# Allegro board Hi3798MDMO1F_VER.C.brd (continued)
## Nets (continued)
IR_IN: D3.1 J3.3 R140.1 U1.58
LED0_BASE: R26.2 R67.2 U1.151
LED0_LINK_ACT: R30.2 R79.2 U1.150
LED_CTRL: R3.1 R31.2 R77.1 U1.57
LED_GREEN: J3.1 LED1.3 Q2.3 R34.2
LED_RED: J3.5 LED1.1 Q1.3 R2.2 R22.1
NF_ALE_EMMC_PWREN: U1.80 U19.17
NF_CLE: U1.81 U19.16
NF_CSN0_EMMC_CMD: R212.2 U1.82 U19.9 U22.W5
NF_DQ0_EMMC_D0: R189.2 U1.77 U19.29 U22.H3
NF_DQ1_EMMC_D1: R12.2 U1.76 U19.30 U22.H4
NF_DQ2_EMMC_D2: R29.2 U1.75 U19.31 U22.H5
NF_DQ3_EMMC_D3: R58.2 U1.73 U19.32 U22.J2
NF_DQ4_EMMC_D4: R176.2 U1.72 U19.41 U22.J3
NF_DQ5_EMMC_D5: R177.2 U1.71 U19.42 U22.J4
NF_DQ6_EMMC_D6: R188.2 U1.70 U19.43 U22.J5
NF_DQ7_EMMC_D7_BOOT_SEL0: R33.1 R202.2 U1.69 U19.44 U22.J6
NF_RDY0_EMMC_RST: C115.1 R203.2 U1.85 U19.7 U22.U5
NF_REN_EMMC_CLK: R59.1 U19.8 U22.W6
NF_WEN_EMMC_DET: R56.2 U1.79 U19.18
NF_WP: R89.1 R215.2 U19.19
PWR_OFF/ON: R40.1 R41.1 U1.102
RECOVERY: C138.2 R25.2 S1.2 U1.103
RF0: C89.1 L1.2 U7.3
RF1: C56.1 L7.2 U2.7 U7.2
RFF0: C88.1 J9.1 L1.1
RFF1: C50.1 J8.1 L7.1
RX+_PHY0: R97.1 U1.143 U8.2 U8.7
RX-_PHY0: R96.1 U1.142 U8.1 U8.8
SPDIF_OUT_BOOT_SEL1: R39.1 U1.117
STANDBY_PWROFF: C119.1 LB3.2 R5.1 R47.1 R73.1 R88.1 R98.1
TX+_PHY0: R93.1 U1.146 U8.4 U8.5
TX-_PHY0: R94.1 U1.145 U8.3 U8.6
UART0_RXD: J18.2 R136.1 U1.60
UART0_TXD: J18.3 R135.2 U1.61
USB0_DM: C103.1 D5.1 J12.2 U1.140
USB0_DP: C106.1 D4.1 J12.3 U1.141
USB01_1V1: C334.1 C336.1 LB31.2 U1.137
USB01_3V3: C10.1 C182.1 LB20.2 U1.139
USB1_DM: J2.4 U1.135 U2.4 U7.7
USB1_DP: J2.3 U1.136 U2.2 U7.6
USB2_DM: D7.1 J7.2 U1.89
USB2_DP: D6.1 J7.3 U1.90
USB03_VBUS: C60.1 C265.1 C372.1 J7.1 J12.1 LB2.1 U26.5
USB_BOOT: R42.2 U1.108
VDAC_3V3: C9.1 C85.1 LB14.2 U1.112
XIN: C364.1 R1.2 U1.63 X2.1
XOUT: R1.1 R14.1 U1.64
$4N588: C84.1 R10.1 R52.1 U15.5
$4N589: L4.1 U15.3
$4N593: C30.1 R6.2 R47.2 U15.1
$4N676: C43.1 C71.1 R7.2 R21.1
$4N677: C76.1 R53.1 R70.1 R99.2 U11.6
$4N679: L2.1 U11.3
$4N687: C8.1 R73.2 U11.1
$4N714: C82.1 R13.2 R101.1 R110.1 U13.6
$4N715: C45.1 C72.1 R23.1 R102.2
$4N716: R102.1 R110.2
$4N719: L3.1 U13.3
$4N724: C5.1 R5.2 U13.1
$4N894: R7.1 R70.2
$4N901: R100.1 R105.1 U14.5
$4N903: D2.1 R95.1 U14.1
$4N904: C83.2 R104.1
$4N905: C24.1 C83.1 U14.6
$4N906: R4.2 U14.7
$4N919: C44.1 U14.8
$4N923: C65.1 R95.2
$4N925: C65.2 L5.1 U14.3
$4N944: J1.1 J5.2 J10.1 R81.1
$5N541: Q4.3 R118.2 R144.2
$5N542: C6.2 Q13.1 Q14.1 R118.1
$5N549: Q4.1 R98.2
$6N188: C365.1 R14.2 X2.3
$6N1407: R173.1 U1.149
$6N2385: R82.2 R85.2 U1.138
$6N2411: C136.1 R42.1 S2.1 S2.2
$6N2437: R59.2 U1.84
$6N2445: C118.1 LB3.1 U1.59
$7N1408: C250.2 U1.113
$7N1763: R32.2 U1.111
$7N2000: R24.2 R87.2 U1.87
$8N1506: R45.1 U1.54
$8N1694: R18.2 U1.17
$8N1695: R35.2 U1.18
$8N1696: R36.2 U1.14
$8N1697: R37.2 U1.15
$9N2352: C255.2 U1.55
$9N2555: C122.1 LB5.2 U1.65
$10N1056: C328.1 R11.2 R15.1
$10N1121: R46.2 U3.L8
$11N1393: C330.1 R16.2 R17.1
$11N1414: R71.2 U6.L8
$12N1655: R49.2 U19.38
$12N1661: R57.1 U19.39
$12N1670: C123.1 C124.1 U22.K2
$13N803: R220.1 U26.3
$13N804: R106.2 U26.4
$14N721: Q2.1 R22.2
$14N731: Q1.1 R3.2
$15N1021: C351.2 R193.1
$15N1022: C55.1 R27.2 U5.2
$15N1025: C317.1 R19.1 R27.1 R193.2
$15N1029: C55.2 R19.2 R74.2 R146.1 U5.3
$15N1031: C54.2 R28.1 U5.13
$15N1032: C54.1 R20.1 R72.1 R145.1 U5.12
$15N1036: C350.1 R194.2
$15N1037: C316.1 R20.2 R28.2 R194.1
$15N1074: R43.2 R44.1 R48.2
$15N1075: R43.1 U5.11
$15N1082: C32.1 U5.7
$15N1083: C33.2 U5.6
$15N1085: C32.2 U5.8
$15N1114: C363.1 R66.1 U5.5
$16N1065: C154.1 C297.1 T2.7
$16N1066: J25.9 R67.1
$16N1067: J25.11 R79.1
$16N1068: J25.7 J25.8 R270.2
$16N1069: R271.2 T2.15
$16N1070: R269.2 T2.10
$16N1072: J25.6 T2.9
$16N1073: J25.3 T2.11
$16N1074: C23.1 R269.1 R270.1 R271.1 R272.1
$16N1075: J25.1 T2.16
$16N1076: J25.2 T2.14
$16N1077: J25.4 J25.5 R272.2
$16N1078: C153.1 C307.1 T2.2
$16N1097: R96.2 T2.8
$16N1098: R97.2 T2.6
$16N1099: R94.2 T2.3
$16N1100: R93.2 T2.1
$18N796: D19.1 R268.1

Pads without a net: ID1 1; ID2 1; ID3 1; ID4 1; ID5 1; ID6 1; J2 1 6 8 11; J26 14; M20 1; M21 1; T2 4 5 12 13; U1 56 99 100 101 152 153 154 155 156 157 159 160 161 162; U2 3; U3 J1 J9 L1 L9; U6 J1 J9 L1 L9; U7 4 9 10; U11 5; U13 5; U19 3 4 5 6 10 11 14 15 20 21 22 26 27 28 33 35 40 45 46 47; U22 A4 A6 A9 A11 AA1 AA2 AA7 AA8 AA9 AA10 AA11 AA12 AA13 AA14 AE1 AE14 AG2 AG13 AH4 AH6 AH9 AH11 B2 B13 D1 D14 H1 H2 H6 H7 H8 H9 H10 H11 H12 H13 H14 J1 J7 J8 J9 J10 J11 J12 J13 J14 K1 K3 K5 K7 K8 K9 K10 K11 K12 K13 K14 L1 L2 L3 L4 L12 L13 L14 M1 M2 M3 M5 M8 M9 M10 M12 M13 M14 N1 N2 N3 N10 N12 N13 N14 P1 P2 P3 P10 P12 P13 P14 R1 R2 R3 R5 R12 R13 R14 T1 T2 T3 T5 T12 T13 T14 U1 U2 U3 U6 U7 U10 U12 U13 U14 V1 V2 V3 V12 V13 V14 W1 W2 W3 W7 W8 W9 W10 W11 W12 W13 W14 Y1 Y3 Y6 Y7 Y8 Y9 Y10 Y11 Y12 Y13 Y14

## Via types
v1: diameter 0.457, hole 0.203, TOP to BOTTOM, 423 vias
v2: diameter 0.508, hole 0.254, TOP to BOTTOM, 1803 vias
v3: diameter 0.635, hole 0.305, TOP to BOTTOM, 36 vias

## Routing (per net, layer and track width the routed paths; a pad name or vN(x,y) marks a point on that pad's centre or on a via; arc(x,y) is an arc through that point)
1V1_CORE: length 71.9
  TOP w0.203: U1.168 v2(59.58,56.7) ; U1.118 78.22,59.92 v1(78.4,59.74) ; v2(59.58,49.75) 59.33,49.5 U1.186 ; U1.202 v2(59.58,43.1) ; U1.193 v2(59.58,46.7) ; U1.134 71.82,60.03 v1(72.1,59.76) ; U1.86 83.18,49.9 82.86,49.58 v1(82.86,49.52) ; v2(59.66,38.3) U1.214 ; U1.30 v2(72.22,36.47) ; v1(82.86,57.7) 82.86,57.68 82.86,57.68 82.86,57.68 83.04,57.5 U1.105 ; U1.39 v2(75.82,36.47) ; U1.4 v2(61.82,36.47) ; U1.10 v2(64.22,36.47) ; U1.49 v2(79.82,36.47) ; U1.158 v2(62.22,59.58) ; U1.78 v1(82.86,46.7) ; U1.180 v2(59.58,51.9)
  TOP w0.381: v2(85.7,35.02) 85.97,34.75 89.5,34.75 90.71,33.54 90.71,26.53 C82.2
  TOP w0.508: R101.2 C82.2
  BOTTOM w0.305: C189.1 59.58,51.9 v2(59.58,51.9) ; C62.1 59.52,56.76 v2(59.58,56.7) ; v2(64.22,36.47) 64.22,36.44 C19.1 ; C193.1 61.82,36.44 61.82,36.44 v2(61.82,36.47) ; v2(79.82,36.47) 79.82,36.44 79.82,36.44 C64.1 ; C107.1 v2(72.22,36.47) ; C129.1 v1(82.86,49.52) ; C120.1 v2(75.82,36.47) ; v1(82.86,57.7) 82.86,57.71 82.98,57.83 C128.1
  BOTTOM w0.381: C127.1 59.66,38.3 v2(59.66,38.3) 59.67,38.3 60.55,38.3 60.55,38.3 60.84,38.3 v2(62.18,39.64) ; C121.1 59.58,43.1 v2(59.58,43.1) v2(62.17,43.1) ; v2(61.54,51.9) v2(59.58,51.9) ; C66.1 78.61,59.95 v1(78.4,59.74) ; C130.1 83.54,46.7 v1(82.86,46.7) ; v2(62.22,59.58) 62.22,59.61 62.23,59.61 C70.1 ; LB31.1 72.86,58.1 73.25,58.49 73.25,59.43 72.92,59.76 v1(72.1,59.76) 72.03,59.82 C126.1 ; v2(62.17,46.7) v2(59.58,46.7) 59.4,46.52 C73.1 ; v2(79.82,36.47) v2(79.82,38.29) ; v2(64.22,36.47) 64.22,37.45 64.21,37.46 64.22,37.47 v2(64.22,38.73) ; v2(62.71,38.73) 61.82,37.84 v2(61.82,36.47) ; v2(72.22,36.47) v2(72.22,38.29) ; C1.1 59.19,49.75 v2(59.58,49.75) v2(61.54,49.75) ; v2(61.54,56.7) v2(59.58,56.7) ; v2(75.82,36.47) v2(75.82,38.29)
  vias: v2(76.94,59.56) v2(76.94,58.82) v2(81.71,45.18) v2(81.92,37.79) v2(82.55,37.03) v2(82.68,37.79) v2(83.19,36.39) v2(83.31,35.5) v2(84.18,35.02) v2(84.18,34.26) v2(84.94,35.02) v2(84.94,34.26) v2(85.7,34.26)
1V1_CPU: length 13.6
  TOP w0.203: U1.98 85.53,54.7
  TOP w0.381: v2(106.8,62.23) C76.2 R53.2
  BOTTOM w0.381: v2(106.8,62.23) 101.74,62.23 v2(98.01,58.5)
  vias: v1(82.88,53.77) v1(82.86,52.44) v1(82.86,51.78) v2(85.01,52.32) v2(85.45,54.53) v2(85.45,53.71) v2(85.45,52.9) v2(93.98,54.76) v2(93.95,53.92) v2(94.95,53.89) v2(96.01,53.89) v2(98.26,55.52) v2(98.26,54.76) v2(98.26,53.99) v2(99.02,55.52) v2(99.02,54.76) v2(99.02,53.99)
1V5_DDR3: length 66.4
  TOP w0.203: v2(81.17,36.47) 81.42,36.22 U1.53 ; U1.13 v2(65.42,36.46) ; U1.174 v2(59.58,54.3) ; U1.165 v2(59.58,57.9) ; U1.183 v2(59.58,50.7) ; U1.208 v2(59.58,40.7) ; U1.7 v2(63.02,36.46) ; U1.25 v2(70.22,36.47) ; U1.190 59.33,47.9 v2(59.58,47.65) ; U1.35 v2(74.22,36.47) ; U1.199 v2(59.58,44.3) ; U1.205 v2(59.58,41.9) ; U1.171 v2(59.58,55.5) ; U1.196 v2(59.58,45.5) ; U1.44 v2(77.82,36.47) ; U1.16 v2(66.62,36.46)
  TOP w0.254: 14.27,53.54 14.27,52.45 13.08,51.26 v2(13.08,50.62) ; U6.F1 49.24,38.74 v1(49.24,39.26) ; C84.2 R10.2 6.63,50.65 v2(6.6,50.62)
  TOP w0.305: U6.D9 v1(50.85,31.79) ; v1(42.05,39.36) U6.R1 ; U3.C9 v1(51.65,48.21) ; U3.K8 v1(46.45,49.95) ; U6.C1 v1(51.65,39.29) ; v1(48.44,50.88) 48.45,50.87 U3.G7 ; U6.N9 v1(43.65,31.79) ; U3.F1 49.25,55.77 49.25,55.77 v1(49.25,55.82) ; U3.R9 v1(42.05,48.21) ; U3.D9 v1(50.85,48.21) ; U6.G7 v2(48.05,34.34) ; U6.R9 42.05,32.07 41.83,31.85 v1(41.83,31.85) ; U3.B2 v1(52.85,54.75) U3.A1 ; v1(43.65,39.36) U6.N1 ; U6.C9 v1(51.65,31.79) ; U6.A8 v1(53.86,33.14) ; U6.D2 v1(51.25,37.54) ; U6.E9 v1(50.05,31.79) ; U6.K8 v1(46.45,33.54) ; U6.B2 v1(52.85,38.35) U6.A1 v1(53.25,39.29) ; U1.1 v2(60.57,36.52) ; U3.H9 v1(47.65,48.21) ; U6.K2 v1(45.65,38.34) ; U3.E9 v1(50.05,48.21) ; v1(51.65,55.69) U3.C1 ; U6.H9 v1(47.65,31.79) ; v1(42.05,55.77) U3.R1 ; v1(43.65,55.77) U3.N1 ; U3.K2 v1(45.65,54.75) ; U3.N9 v1(43.65,48.21) ; U3.A8 v1(53.65,49.15) ; U3.H2 v2(48.05,54.75) ; U6.H2 v1(48.05,38.34) ; U3.D2 v1(51.25,53.95)
  BOTTOM w0.254: v2(6.6,50.62) v2(13.08,50.62)
  BOTTOM w0.305: v2(77.82,36.47) 77.82,36.44 77.83,36.44 C49.1 ; C52.1 81.18,36.43 81.17,36.44 v2(81.17,36.47) ; C101.1 59.58,54.3 v2(59.58,54.3) ; C109.1 63.02,36.46 v2(63.02,36.46) ; v2(70.22,36.47) C99.1 ; v2(59.58,55.5) 59.55,55.47 C137.1 ; v2(59.58,41.9) 59.58,41.9 C94.1 ; v2(65.42,36.46) 65.43,36.45 C117.1 ; C97.1 59.57,50.69 v2(59.58,50.7) ; C102.1 66.6,36.44 v2(66.62,36.46) ; v2(59.58,57.9) 59.58,57.9 C131.1 ; C48.1 60.55,36.5 v2(60.57,36.52) ; v2(59.58,40.7) 59.58,40.71 C92.1 ; C233.1 v2(74.22,36.47)
  BOTTOM w0.381: C104.1 59.57,44.29 v2(59.58,44.3) ; C96.1 v2(59.58,47.65) ; C98.1 v2(59.58,45.5) ; v1(49.25,55.82) 49.28,55.85 C208.1 R54.1 ; v1(49.24,39.26) 49.24,39.81 49.5,40.07 C223.1 R78.1
  vias: v2(15.24,54.69) v2(15.24,53.8) v2(16.13,54.69) v2(16.13,53.8) v2(56.95,36.19) v2(56.95,35.43) v2(57.66,36.19) v2(57.66,35.43) v2(58.39,36.21) v2(58.42,35.43) v2(59.13,35.4) v2(59.16,36.19)
3V3: length 68
  TOP w0.381: J18.4 88.91,20.78 88.11,19.98 R135.1 R136.2 84.36,19.98 v2(84.07,20.27) ; R6.1 9.99,52.95 v2(9.91,53.04) ; R178.2 124.95,20.07 v2(125.15,20.26) ; R105.2 v2(15.86,62.01) ; R140.2 123.93,20.08 v2(123.72,20.29) ; R88.2 91.25,37.19 93.37,35.07 v2(93.37,34.97) 93.45,34.89 93.45,26.31 v2(93.34,26.21)
  BOTTOM w0.381: R31.1 v2(103.99,15.77) ; v2(93.37,34.97) 93.4,34.97 96.9,38.47 96.9,43.13 95.82,44.21 C13.1 86.91,44.21 C108.1 LB5.1 ; v2(93.34,26.21) 91.82,24.68 91.82,22.42 90.5,21.09 J18.4 ; R2.1 110.26,20.88 v2(112.9,18.24) ; v2(4.06,53.04) v2(9.91,53.04)
  BOTTOM w0.508: v2(10.31,62.01) v2(15.86,62.01)
  vias: v2(2.32,48.08) v2(2.38,48.8) v2(3.09,48.76) v2(3.06,48.04) v2(3.83,48.78) v2(3.83,48.06) v2(72.52,15.45) v2(72.52,14.56) v2(72.52,13.67) v2(73.41,15.45) v2(73.41,14.56) v2(73.41,13.67) v2(82.3,15.45) v2(83.03,22.7) v2(83.03,21.94) v2(83.06,15.45) v2(83.79,22.7) v2(83.79,21.94) v2(83.82,15.45) v2(84.58,15.45) v2(113.39,56.23) v2(113.39,55.42) v2(114.2,57.07) v2(114.2,56.23) v2(114.2,55.42) v2(115.44,17.49) v2(115.42,16.73) v2(116.18,17.47) v2(116.18,16.73) v2(116.94,16.71) v2(116.97,17.44) v2(123.21,53.08) v2(123.71,52.56) v2(123.77,53.67) v2(123.75,21.07) v2(124.29,53.15) v2(124.35,54.21) v2(124.43,20.29) v2(124.46,21.07) v2(124.85,53.71) v2(125.17,21.07)
3V3_IR: length 9.1
  BOTTOM w0.508: v2(127.13,17.1) 120.78,17.1 119.88,16.2 J3.2
3V3_MOS: length 246.1
  TOP w0.203: v1(82.86,48.52) 83.04,48.7 U1.83 ; U1.104 83.04,57.1 v1(82.86,56.92) ; U1.74 83.11,45.1 v1(82.86,45.35) ; v1(77.6,59.74) 77.42,59.92 U1.120
  TOP w0.381: J25.10 46.82,83.18 46.28,83.72 43.99,83.72 43.18,82.91 43.18,76.81 43.63,76.36 R26.1 44.18,75.47 43.31,74.6 v2(43.31,73.48) ; v2(38.05,75.03) D19.2 ; J25.12 60.43,80.37 v2(60.43,75.84) 60.43,75.83 60.43,75.05 60.43,72.3 59.94,71.82 R30.1 ; v2(77.6,91.01) 77.6,90.38 76.32,89.1 R25.1 ; R41.2 v2(87.27,57.85)
  TOP w0.508: v2(77.6,91.01) 94.87,91.01 97.42,88.46 99.7,88.46 101.48,90.25 116.57,90.25 118.75,88.07 v2(118.75,82.12)
  TOP w0.762: 115.38,66.78 121.56,72.97 123.44,72.97
  TOP w1.016: v2(15.49,25.48) v2(16.51,24.46) 27.69,13.29 69.34,13.29 71.25,15.19 71.25,17.6 73.54,19.9 Q13.3
  BOTTOM w0.305: v1(82.86,56.92) 83.07,56.71 C199.1
  BOTTOM w0.381: C197.1 v1(82.86,45.35) 81.99,46.22 v2(79.76,46.22) ; R39.2 C245.1 77.72,59.86 v1(77.6,59.74) 78.46,58.88 78.46,56.91 v2(78.08,56.53) ; v2(60.43,75.84) 58.33,73.74 57.02,73.74 55.5,72.21 46.36,72.21 45.08,73.48 v2(43.31,73.48) 41.02,73.48 39.47,75.03 v2(38.05,75.03) ; v1(82.86,56.92) 81.96,56.92 LB14.1
  BOTTOM w0.508: J25.12 61.85,86.16 61.85,87.07 65.79,91.01 v2(77.6,91.01)
  BOTTOM w0.762: v2(123.19,72.93) v2(123.19,73.77) 118.75,78.21 v2(118.75,82.12)
  BOTTOM w1.016: v2(16.51,24.46) v2(15.49,25.48) 13.56,27.41 LB4.2
  vias: v2(65.84,56.53) v2(66.55,56.53) v2(68.5,56.51) v2(69.22,56.51) v2(70.23,41.22) v2(70.99,41.22) v2(73.61,56.56) v2(74.32,56.56) v2(78.08,41.93) v2(79.12,55.95) v2(79.15,55.21) v2(79.88,55.95) v2(79.86,55.19) v2(79.86,47.97) v2(112.33,67.9) v2(112.35,68.68) v2(113.07,68.69) v2(113.06,67.95) v2(118.31,54.7) v2(118.31,53.97) v2(119.08,54.7) v2(119.08,53.97) v2(122.92,47.45) v2(122.88,46.65) v2(123.64,47.45) v2(123.64,46.65) v2(124.38,47.48) v2(124.36,46.65)
3V3_MOS_FLASH: length 53.4
  TOP w0.203: U22.Y4 U22.AA3
  TOP w0.254: v2(101.07,43.63) 100.43,44.26 99.82,44.26 98.26,45.83 U19.24 ; v2(102.76,26.75) U19.34 ; U22.K6 104.76,35.78 v1(104.4,36.14) ; v1(105.76,39.64) U22.W4 U22.Y4 ; v2(106.8,41.71) 106.26,41.16 U22.AA3 ; 109.73,44.65 109.76,44.67 U19.1 ; v1(104.4,36.14) 104.76,36.5 U22.M6 104.76,37.17 v1(104.71,37.22) 105.19,37.22 U22.N5 ; v1(104.4,36.14) 102.59,36.14 102.23,36.5 102.23,38.28 102.6,38.65 U22.T10 102.76,38.65 v1(103.26,38.65) U22.U9 103.26,39.26 v1(102.86,39.66) ; v2(105.26,41.71) U22.AA5 ; U19.37 104.26,29.15 v2(104.38,29.28) ; v2(104.51,46.51) 104.26,46.76 U19.12
  TOP w0.381: R202.1 107.96,24.58 v2(107.83,24.45) ; R188.1 106.69,24.58 v2(106.56,24.45) ; R176.1 v2(104.15,24.45) ; R58.1 v2(101.98,24.45) ; v2(99.44,24.45) 99.44,24.96 99.44,24.96 R12.1 ; v2(102.74,24.45) 103,24.71 R49.1 ; R29.1 v2(100.71,24.45) ; R177.1 v2(105.42,24.45) ; R189.1 v2(97.56,25.06) ; v2(106.8,41.71) 106.8,41.88 106.39,42.29 105.51,42.29 105.26,42.04 v2(105.26,41.71)
  BOTTOM w0.305: v2(104.51,46.51) 104.51,45.74 C143.1
  BOTTOM w0.381: v1(103.26,38.65) 103.09,38.81 C105.1 102.61,39.42 102.85,39.66 102.85,39.66 v1(102.86,39.66) 102.97,39.77 R212.1 ; v1(105.76,39.64) 105.95,39.83 C63.1 107.43,39.83 R203.1 ; v1(105.76,39.64) 105.76,40.57 C324.1 105.26,41.07 v2(105.26,41.71) ; v1(105.76,39.64) 105.74,39.64 105.13,39.03 105.13,37.8 105.34,37.59 C93.1 104.92,37.01 v1(104.71,37.22) 104.71,36.46 v1(104.4,36.14) 104.39,36.14 C100.1 ; v2(104.38,29.28) 104.42,29.24 C142.1 ; v2(106.8,41.71) 106.8,41.94 C323.1 ; v2(101.07,43.63) 100.37,43.63 99.94,44.06 R215.1 ; v2(103.94,44.67) 104.53,45.27 C143.1
  BOTTOM w0.508: 101.68,34.79 102.53,34.79 103.57,35.82 C100.1
  vias: v2(99.19,34.56) v2(99.9,34.56) v2(111.71,44.3) v2(111.7,43.56) v2(112.45,44.31) v2(112.48,43.57)
3V3_WIFI: length 3.2
  BOTTOM w0.254: LB4.1 11.95,33.33 C15.1 11.9,34.86 C61.1
  vias: v2(10.29,35.79) v2(10.28,35.06) v2(11.02,35.8)
5V0: length 10.3
  TOP w0.254: v2(22.99,65.23) 21.97,64.21 R4.1 ; R144.1 25.55,68.32 Q14.2
  BOTTOM w0.254: v2(22.99,65.23) 22.99,67.07 v2(24.92,69)
5V0_MOS: length 27.8
  TOP w0.381: R179.1 108.96,69.35 108.76,69.15 90.96,69.15 v2(90.71,68.9)
  TOP w0.457: D20.2 41.66,73.99 v2(42.93,72.72)
  BOTTOM w0.381: LB2.2 90.71,73.42 v2(90.71,68.9)
  vias: v2(29.34,67.64) v2(29.34,66.75) v2(30.23,67.64) v2(30.23,66.75) v2(90.29,76.64) v2(90.28,75.92)
5V0_MOS_HDMI: length 17.3
  TOP w0.254: J26.18 34.57,83.08 35.15,82.49
  TOP w0.508: R186.2 v2(38.2,80.84) ; 35.15,82.49 35.53,82.11 v2(38.2,82.11) 41.07,82.11 41.66,81.53 R187.2 41.66,80.81 C150.1 D20.1 38.99,78.5 U4.5
  BOTTOM w0.508: v2(38.2,82.11) v2(38.2,80.84)
AVDD11_PLL012: length 1.2
  TOP w0.203: v1(82.86,42.96) 82.86,42.95 83.11,42.7 U1.68
AVDD33_PLL01: length 1.2
  TOP w0.203: U1.66 83.11,41.9 82.86,41.65 v1(82.86,41.64)
AVDD33_USB2: length 1.1
  TOP w0.203: U1.88 v1(82.86,50.7)
GND: length 442.5
  TOP w0.089: U22.Y2 107.01,40.9 v2(107.7,40.9)
  TOP w0.127: v1(55.42,47.92) 55.45,47.9 v1(57.45,47.9) ; RN6.3 v2(27.69,35.77) ; U1.177 58.65,53.1 ; v1(45.65,37.54) 45.04,37.54 44.81,37.31 44.81,36.59 44.04,35.83 39.9,35.83 39.7,36.04 ; v1(41.15,46.48) 41.44,46.78 43.04,46.78 43.32,47.06 v1(43.76,47.06) ; 41,49.94 42.25,49.94 42.44,50.13 42.44,50.93 ; 50.44,32.74 50.44,32.74 ; 50.44,32.74 U6.D8 ; 50.44,32.74 50.44,31.4 50.83,31.02 v2(50.83,30.99) 50.99,30.83 v2(52.95,30.83) v2(57.19,30.83) v2(59.64,30.83) 60.02,30.83 63.02,33.83 v1(63.02,34.27) ; v1(64.22,34.27) 64.22,33.49 60.29,29.56 v2(59.87,29.56) v2(55.44,29.56) v2(51.1,29.56) ; v1(36.84,50.8) 37.43,51.39 45.75,51.39 v1(45.78,51.35) ; RN2.3 v2(27.69,54.31) ; 28.31,45.8 v2(27.05,45.8) ; 28.31,50.37 v2(27.69,50.37) ; RN5.2 v2(27.05,43) ; v1(57.44,39.5) 56.46,39.5 v1(55.83,38.86) 55.54,38.57 55.54,37.05 v1(54.38,35.89) 53.79,35.3 50.04,35.3 v2(49.96,35.22) ; v1(50.37,46.18) 50.05,46.18 v1(49.01,47.22) 48.45,47.79 U3.G9 ; 42.44,50.93 38.2,50.93 v1(38.04,50.76) ; 42.44,50.93 42.86,50.93 43.25,50.55 v1(43.25,49.95) 43.25,49.36 42.85,48.96 U3.P9 ; v1(35.92,51.74) 36.35,52.18 44.3,52.18 v1(44.53,52.41) ; v1(39.24,53.16) 39.44,52.96 42.99,52.96 43.18,53.15 v1(43.23,53.15) 43.24,53.17 v1(43.24,53.95) ; RN4.3 v2(27.69,39.7) ; v1(54.74,45.27) 54.38,44.91 v2(51.82,44.91) 50.67,44.91 48.49,42.73 48.49,39.68 v1(48.45,39.64) ; v2(54.51,53.77) 53.41,52.67 51.32,52.67 v1(51.18,52.81) ; U6.P1 42.85,38.43 43.26,38.02 43.26,36.87 42.95,36.57 40.62,36.57 39.73,37.46 39.73,37.69 39.35,38.07 39.01,38.07 ; RN7.2 v2(27.05,57.61) ; v1(53.85,47.96) 53.67,47.78 v1(52.45,47.78) 50.62,47.78 50.44,47.96 50.44,49.15 U3.D8 ; U3.E2 50.05,54.34 ; U1.211 58.71,39.5 ; U6.P9 42.85,32.5 43.26,32.91 43.26,34.08 42.8,34.54 38.48,34.54 37.9,35.12
  TOP w0.152: v1(39.31,46.5) 40.35,47.54 42.34,47.54 42.85,48.05 42.85,48.21 ; U3.P1 42.85,54.94 43.26,54.53 43.26,53.97 v1(43.24,53.95) 43.23,53.94 41.94,53.94 41.66,54.22 41.66,54.48 41.25,54.89 U3.T1
  TOP w0.203: v1(79.17,59.74) 79.42,59.99 U1.115 79.42,61.89 79.53,61.99 v2(79.53,62.3) ; U1.97 83.04,54.3 v1(82.86,54.48) ; U1.110 81.42,61.67 81.25,61.84 v2(81.25,62.22) ; v1(82.86,42.3) U1.67 84.93,42.3 v2(85.12,42.49) ; U22.Y5 U22.AA6 ; v1(57.44,39.5) U1.211 ; v2(85.17,40.21) 85.08,40.3 U1.62 ; U1.19 67.82,34.14 v1(67.82,34.14) ; v1(57.38,53.1) U1.177 ; U1.94 v1(82.86,53.1) ; v1(46.33,46.93) 46.46,47.06 46.46,49.16 U3.J8
  TOP w0.229: v1(105.25,36.15) 105.75,35.65 U22.K4
  TOP w0.254: U19.25 98.26,29.42 v2(98.78,29.94) ; v2(119.13,65.79) 119.13,65.34 S2.5 ; 104.08,74.15 v2(104.08,74.12) 104.51,74.55 U5.10 ; v1(40.87,55.59) 41.25,55.22 U3.T1 ; v2(106.04,41.71) 105.76,41.42 U22.AA4 ; C150.2 40.85,79.42 40.59,79.16 v2(40.16,79.16) ; U22.AA6 104.76,41.34 v2(104.39,41.71) ; C71.2 v2(86.15,65.15) ; 118.23,77.89 C17.2 117.48,77.19 ; v2(103.63,29.28) 103.76,29.15 U19.36 ; J26.17 v2(34.07,82.72) ; 109.75,26.94 109.76,26.95 U19.48 109.76,29.3 109.75,29.3 ; C363.2 98.49,70.11 v2(98.55,70.05) ; 109.25,46.42 109.26,46.44 U19.2 ; J26.5 28.07,82.98 v2(28.12,82.94) ; 98.76,46.42 98.76,46.43 U19.23 ; J26.8 v2(29.57,82.95) ; v1(51.36,40.3) 50.85,39.79 U6.D1 U6.E1 ; v1(40.36,53.97) 40.16,53.97 39.7,54.42 v1(39.37,54.42) ; U19.13 103.76,46.51 v2(103.75,46.51) ; 105.26,40.69 U22.Y5 ; 41,49.94 v1(40.56,49.94) ; C72.2 88.98,64.28 v2(89.15,64.46) ; J26.11 v2(31.07,82.98) ; U6.G8 U6.G9 ; J26.2 v2(26.57,82.95)
  TOP w0.305: v1(52.45,55.92) U3.B1 ; U6.E1 U6.E2 v1(50.45,37.53) ; U24.8 U24.3 ; U6.T1 41.25,39.33 41.26,39.35 v1(41.26,39.36) ; v1(53.86,32.34) U6.A9 U6.B9 ; U3.G8 U3.G9 ; v1(50.45,49.95) U3.E8 ; U6.P9 v1(42.85,31.79) ; U3.G1 48.34,55.26 v1(48.34,55.87) ; v2(52.85,53.95) U3.B3 v2(52.85,53.14) ; v1(44.45,55.77) U3.M1 ; U6.T9 v1(40.55,32.34) ; v1(43.76,47.06) 44.45,47.74 U3.M9 ; v1(50.85,55.72) U3.D1 U3.E1 ; v1(51.25,49.95) U3.D8 ; U3.F9 v1(49.25,48.21) ; 42.77,39.26 42.85,39.19 U6.P1 ; v1(52.45,39.29) U6.B1 ; U6.G1 v1(48.45,39.64) ; v1(40.54,48.7) 41.2,48.7 U3.T9 ; U6.G9 v1(48.45,31.79) ; U6.F9 v1(49.25,31.79) ; 42.85,48.21 U3.P9 ; U23.8 U23.3 ; U6.J2 v1(47.25,38.35) ; U6.M1 v1(44.45,39.36)
  TOP w0.381: J3.4 123.88,16.05 ; J3.4 124.9,14.72 ; J3.4 122.87,14.72 ; J3.4 123.88,13.4 ; v2(40.83,77.15) 41.02,76.96 41.02,75.89 40.53,75.4 C149.2 ; 13.75,87.78 13.76,87.78 J1.3 16.45,89.32 16.45,89.32 ; 124.01,12.5 D3.2 125.08,13.57 ; v2(40.1,77.16) 40.1,76.91 40.34,76.66 R8.1 ; U6.B3 v1(52.85,37.55)
  TOP w0.457: 95.36,50.97 v2(95.36,50.97) 95.36,50.97 95.36,50.97 ; 95.36,50.97 v2(99.19,50.97) 102.64,50.97 102.64,50.97 v2(103.25,50.97) 105.31,50.97 v2(105.41,50.87) v2(106.3,49.98) ; C118.2 v2(86.36,37.04) ; C138.1 75.68,88.08 v2(75.69,88.09) ; v2(89.03,37.16) 89,37.19 C119.2 ; v2(13.45,40.6) 12.87,41.18 J2.2 12.87,45.59 v2(13.46,46.18) ; 90.27,49.45 v2(90.27,49.47) ; v2(107.29,49.37) 107.29,50.39 v2(106.68,51) 105.81,51.87 v2(100.97,51.87) v2(97.42,51.87) v2(93.35,51.87) ; v2(91.29,49.24) 92.12,50.08 v2(93.35,50.08) v2(97.42,50.08) v2(100.97,50.08) v2(103.89,50.08) 104.8,50.08 v2(105.54,49.34)
  TOP w0.508: v2(59.89,58.66) 60.99,58.66 v2(61.75,57.91) v2(62.64,57.01) v2(63.54,56.11)
  BOTTOM w0.127: v1(75.82,34.32) 75.82,34.34 75.82,34.34
  BOTTOM w0.381: J18.1 94.25,21.68 ; J18.1 94.96,20.78 ; J18.1 94.25,19.87 ; 83.22,83.71 J7.5 ; J7.5 84.67,85.16 ; J7.5 81.78,85.16 ; J7.5 83.22,86.61 ; 22.23,85.4 J26.21 ; J26.21 24.41,85.4 ; J26.21 23.32,87.39 ; J26.21 23.32,83.42 ; 15.68,91 J10.2 11.82,91 ; 12.87,41.12 J2.2 12.87,44.95 ; J7.6 83.22,79.61 ; J7.6 84.67,78.16 ; J7.6 81.78,78.16 ; J7.6 83.22,76.71 ; 77.78,83.71 J7.7 ; J7.7 77.78,86.61 ; J7.7 79.23,85.16 ; J7.7 76.34,85.16 ; v2(66.33,61.98) 66.49,61.98 66.78,61.69 C248.2 ; 69.94,78.16 J12.6 ; J12.6 71.38,79.61 ; J12.6 72.83,78.16 ; J12.6 71.38,76.71 ; 6.6,68.01 J6.1 ; J6.1 5.45,69.17 ; J6.1 6.6,70.32 ; J6.1 7.76,69.17 ; 76.34,78.16 J7.8 ; J7.8 79.23,78.16 ; J7.8 77.78,79.61 ; J7.8 77.78,76.71 ; 12.55,14.69 J2.10 ; J2.10 11.58,16.03 ; J2.10 12.55,17.38 ; 108.94,85.97 J34.7 ; J34.7 111.27,87.64 ; J34.7 108.94,89.32 ; J34.7 106.6,87.64 ; 37.82,89.53 J26.22 ; J26.22 36.63,91.36 ; J26.22 39.01,91.36 ; J3.4 123.88,15.94 ; J3.4 122.87,14.72 ; J3.4 123.88,13.51 ; J3.4 124.8,14.72 ; J2.12 16.51,16.03 ; J2.12 15.55,17.38 ; J2.12 15.55,14.69 ; 99.56,12.14 J4.1 ; J4.1 100.71,13.3 ; J4.1 100.71,10.99 ; J4.1 101.87,12.14 ; 71.38,83.71 J12.5 ; J12.5 72.83,85.16 ; J12.5 71.38,86.61 ; J12.5 69.94,85.16 ; J34.8 123.94,89.32 ; J34.8 123.94,85.97 ; J34.8 121.6,87.64 ; J34.8 126.27,87.64 ; 13.76,87.63 13.76,87.63 J1.3 ; J12.7 65.94,86.61 ; J12.7 65.94,83.71 ; J12.7 67.39,85.16 ; J7.4 81.83,78.43 ; J7.4 79.18,78.43 ; J7.4 80.5,77.36 ; 117.33,11.41 LED1.2 ; LED1.2 118.42,12.5 ; LED1.2 117.33,13.59 ; LED1.2 116.14,12.5 ; 46.99,37.03 46.61,36.64 46.61,36.49 ; J26.23 24.51,91.36 ; J26.23 23.32,89.53 ; J26.23 22.13,91.36 ; 65.94,76.71 J12.8 ; J12.8 65.94,79.61 ; J12.8 67.39,78.16 ; D3.2 124.01,12.5 ; D3.2 125.08,11.54 ; D3.2 126.04,12.5 ; D3.2 125.08,13.47 ; J10.3 11.57,89.32 J1.3 ; 37.82,83.32 J26.20 ; J26.20 36.63,85.4 ; J26.20 39.01,85.4 ; J26.20 37.82,87.49 ; J2.9 8.23,16.03 ; J2.9 7.26,14.69 ; J2.9 7.26,17.38 ; 4.26,14.69 J2.7 ; J2.7 3.3,16.03 ; J2.7 4.26,17.38 ; J12.4 69.98,78.43 ; J12.4 67.34,78.43 ; J12.4 68.66,77.36 ; 8.96,83.66 J1.2 ; J1.2 10.28,85.82 ; J1.2 7.64,85.82 ; J1.2 8.96,87.98 ; C289.2 43.25,49.48 v1(43.25,49.95) ; J1.3 16.25,89.32 16.25,89.32 ; J34.6 96.27,87.64 ; J34.6 93.94,85.97 ; J34.6 93.94,89.32 ; J34.6 91.6,87.64
  vias: v1(26.7,32.74) v1(28.14,33.4) v1(29.97,57.61) v1(29.96,45.8) v1(29.98,43) v1(29.97,33.56) v1(30.68,58.2) v1(30.75,47.81) v1(30.76,46.59) v1(30.81,43.55) v1(30.76,30.56) v1(30.92,34.42) v1(30.98,56.66) v1(30.99,54.8) v1(31.01,52.98) v1(31.03,51.13) v1(31.05,49.3) v1(31.1,45.06) v1(31.11,42.03) v1(31.14,40.2) v1(31.17,38.37) v1(31.18,36.52) v1(31.37,47.18) v1(31.59,57.26) v1(31.72,59.26) v1(31.66,48.69) v1(31.69,45.65) v1(31.71,44.45) v1(31.73,42.62) v1(31.9,55.73) v1(31.9,53.89) v1(31.94,52.04) v1(31.85,31.68) v1(31.95,50.21) v1(32.04,41.1) v1(32.07,39.27) v1(32.09,37.44) v1(32.08,35.56) v1(32.27,48.08) v1(32.3,46.26) v1(32.3,45.05) v1(32.51,32.83) v1(32.55,56.36) v1(32.56,49.6) v1(32.63,43.52) v1(32.66,41.69) v1(32.83,54.81) v1(32.84,52.95) v1(32.85,51.13) v1(32.88,45.65) v1(32.97,40.18) v1(32.99,38.34) v1(33.04,36.48) v1(33.07,28.3) v1(33.16,49) v1(33.2,47.16) v1(33.23,44.12) v1(33.49,55.44) v1(33.46,50.53) v1(33.55,42.61) v1(33.57,40.77) v1(33.75,53.88) v1(33.76,52.04) v1(33.8,46.56) v1(33.83,44.72) v1(33.91,39.25) v1(33.92,37.41) v1(33.91,35.09) v1(33.92,33.25) v1(33.93,31.41) v1(33.86,29.44) v1(33.99,57) v1(34.08,49.91) v1(34.1,48.06) v1(34.15,43.2) v1(34.37,51.43) v1(34.53,54.43) v1(34.48,41.67) v1(34.51,39.84) v1(34.68,52.96) v1(34.7,47.46) v1(34.73,45.63) v1(34.75,43.81) v1(34.83,38.33) v1(34.99,50.8) v1(34.99,48.97) v1(35.07,42.28) v1(35.13,35.71) v1(35.13,33.85) v1(35.13,30.22) v1(35.28,52.32) v1(35.41,40.74) v1(35.44,38.91) v1(35.62,48.36) v1(35.64,46.52) v1(35.65,44.7) v1(35.67,42.88) v1(35.68,37.48) v1(35.9,49.89) v1(36,41.34) v1(36.32,53.16) v1(36.33,39.82) v1(36.27,38.08) v1(36.32,32.72) v1(36.32,31.4) v1(36.39,55.7) v1(36.35,34.47) v1(36.35,30.07) v1(36.51,49.28) v1(36.53,47.45) v1(36.55,45.6) v1(36.59,43.77) v1(36.6,41.94) v1(36.75,35.89) v1(36.94,40.41) v1(37.02,54.43) v1(36.98,28.77) v1(37.18,38.96) v1(37.21,36.71) v1(37.21,32.72) v1(37.31,31.4) v1(37.44,50.2) v1(37.44,48.35) v1(37.47,46.52) v1(37.49,44.68) v1(37.52,42.84) v1(37.55,41.01) v1(37.82,39.56) v1(37.82,37.92) v1(38,53.16) v1(38.36,49.25) v1(38.37,47.42) v1(38.38,45.59) v1(38.42,43.74) v1(38.43,41.92) v1(38.39,40.17) v1(38.53,55.7) v1(39.04,49.9) v1(38.99,29.92) v1(39.14,33.55) v1(39.19,32.38) v1(39.29,48.38) v1(39.33,44.66) v1(39.33,42.83) v1(39.28,41.07) v1(39.42,31.06) v1(39.62,39.75) v1(40.24,45.56) v1(40.19,41.97) v1(40.25,43.73) v1(40.54,33.55) v1(41.1,42.87) v1(41.1,31.06) v1(41.17,44.63) v1(41.94,29.89) v1(42,43.78) v1(42.06,45.57) v1(42.44,40.52) v1(43.23,36.76) v1(43.38,41.52) v1(43.61,30.86) v1(43.74,45.87) v1(44.35,57.2) v1(44.4,42.83) v1(44.48,34.89) v1(44.84,53.07) v1(45.69,56.1) v1(45.65,53.95) v1(45.92,39.46) v1(46.23,52.98) v1(46.25,52.16) v1(46.36,58.57) v1(46.96,55.87) v1(47.25,37.55) v1(47.68,51.62) v1(51.69,57.61) v1(51.94,46.31) v1(52.85,50.75) v1(53.16,40.23) v1(53.59,57.61) v1(53.72,54.82) v1(53.65,38.35) v1(54,46.48) v1(53.95,37.15) v1(54.1,56.17) v1(54.43,51.95) v1(54.89,41.86) v1(54.99,39.73) v1(55.25,55.51) v1(55.25,35.08) v1(55.37,57.61) v1(55.45,52.99) v1(55.63,46.71) v1(55.73,44.29) v1(55.75,49.46) v1(55.99,54.27) v1(57.1,36.86) v1(57.33,45.5) v1(57.44,56.7) v1(57.44,55.5) v1(57.44,54.3) v1(57.44,49.5) v1(57.44,44.3) v1(57.44,41.9) v1(57.44,40.7) v1(57.4,38.31) v1(57.46,57.9) v1(57.47,51.9) v1(57.47,50.7) v1(57.45,46.7) v1(57.46,43.1) v1(65.43,34.27) v1(66.62,34.27) v1(68.62,32.13) v1(70.22,34.32) v1(70.62,32.13) v1(72.22,34.32) v1(72.62,32.13) v1(74.22,34.32) v1(74.55,32.13) v1(76.22,32.13) v1(77.82,34.32) v1(78.22,32.13) v1(79.82,34.32) v1(80.22,32.13) v1(85.6,51.94) v1(103.25,37.94) v1(103.91,37.18) v1(104.5,38.65) v1(105.77,38.22) v2(0.76,48.08) v2(0.79,44.66) v2(0.76,42.75) v2(0.81,40.47) v2(0.81,37.89) v2(0.8,35.2) v2(0.89,31.41) v2(0.86,28.29) v2(0.91,25.32) v2(1.02,63.45) v2(1.02,58.37) v2(1.02,53.29) v2(1.04,15.89) v2(1.02,13.29) v2(1.65,92.66) v2(1.65,87.58) v2(1.65,82.5) v2(1.65,77.42) v2(1.65,72.34) v2(1.65,67.26) v2(2.49,14.78) v2(2.92,27.04) v2(2.92,11.38) v2(3.11,30.83) v2(4.47,45.19) v2(4.52,39.38) v2(4.49,35.03) v2(4.57,21.02) v2(4.57,20.13) v2(4.95,54.31) v2(5.32,40.91) v2(5.46,55.69) v2(5.84,27.96) v2(5.97,21.02) v2(5.97,20.26) v2(5.99,19.32) v2(5.97,17.7) v2(6.17,45.26) v2(6.52,55.69) v2(6.82,32.73) v2(6.99,47.57) v2(7.24,20.13) v2(7.37,53.67) v2(7.37,52.4) v2(7.37,51.39) v2(7.37,21.02) v2(7.72,56.72) v2(7.69,55.8) v2(7.73,54.72) v2(7.75,58.24) v2(8.29,92.67) v2(8.43,40.98) v2(8.38,14.7) v2(8.52,90.7) v2(8.52,88.6) v2(8.51,61.8) v2(8.51,60.66) v2(8.51,59.39) v2(8.5,53.93) v2(8.64,82.84) v2(8.64,80.3) v2(8.64,77.76) v2(8.64,75.22) v2(8.56,45.13) v2(8.64,11.38) v2(8.67,72.66) v2(8.67,70.12) v2(8.79,67.84) v2(8.94,17.95) v2(9.1,33.04) v2(9.12,30.54) v2(9.27,52.02) v2(9.27,49.99) v2(9.4,47.57) v2(9.9,53.93) v2(10.03,55.83) v2(9.96,19.42) v2(10.16,81.32) v2(10.16,78.78) v2(10.16,76.24) v2(10.16,73.7) v2(10.19,71.14) v2(10.19,69.23) v2(10.16,23.56) v2(10.16,22.29) v2(10.16,21.02) v2(10.26,91.48) v2(10.41,52.02) v2(10.41,46.05) v2(10.51,32.09) v2(10.86,29.73) v2(10.97,14.72) v2(11.05,47.57) v2(11.21,40.6) v2(11.56,49.99) v2(11.74,27.96) v2(12.07,55.7) v2(12.07,54.69) v2(12.17,75.63) v2(12.19,51.26) v2(12.15,39.25) v2(12.41,30.37) v2(12.62,52.76) v2(13.24,26.12) v2(13.36,20.54) v2(13.46,48.21) v2(13.59,52.77) v2(13.72,11.38) v2(13.84,64.2) v2(13.84,62.93) v2(13.8,50.44) v2(14.09,75.62) v2(14.35,65.73) v2(14.74,39.51) v2(14.7,27.87) v2(14.76,30.41) v2(14.86,52.77) v2(14.94,36.89) v2(14.89,14.69) v2(14.99,63.44) v2(14.99,32.08) v2(14.99,24.21) v2(15.11,38.31) v2(15.24,47.96) v2(15.44,18.48) v2(15.49,51.64) v2(15.49,28.91) v2(15.62,50.37) v2(15.83,75.61) v2(15.97,41.08) v2(16.13,69.79) v2(16.13,68.14) v2(16.13,66.62) v2(16.13,64.84) v2(16.3,91.07) v2(16.31,26.58) v2(16.26,23.07) v2(16.46,30.86) v2(16.89,69.03) v2(17.14,51.89) v2(17.37,49.46) v2(17.37,45.8) v2(17.37,40.72) v2(17.37,35.28) v2(17.37,30.56) v2(17.5,93.06) v2(18.13,69.69) v2(18.05,68.3) v2(18.24,75.55) v2(18.16,29.06) v2(18.16,15.97) v2(18.28,49.31) v2(18.28,45.29) v2(18.28,40.52) v2(18.28,35.32) v2(18.28,30.53) v2(18.42,83.49) v2(18.42,81.45) v2(18.54,53.29) v2(18.8,64.32) v2(18.8,12.02) v2(19.2,69.71) v2(19.22,68.26) v2(19.38,52.1) v2(19.43,20.14) v2(19.6,47.02) v2(19.6,44.99) v2(19.6,40.41) v2(19.6,35.32) v2(19.6,31.19) v2(19.63,28.96) v2(19.69,82.72) v2(19.69,26.95) v2(19.94,23.83) v2(20,93.11) v2(20.06,61.52) v2(20.32,55.07) v2(20.28,49.82) v2(20.41,69.72) v2(20.42,68.24) v2(20.93,48.34) v2(20.92,46.36) v2(20.92,44.4) v2(20.92,42.4) v2(20.92,38.61) v2(20.92,35.32) v2(20.92,31.75) v2(20.96,81.45) v2(20.95,29.57) v2(21.21,52.66) v2(21.29,23.88) v2(21.59,17.99) v2(21.67,25.02) v2(21.95,54.69) v2(21.97,72.2) v2(21.97,71.16) v2(21.97,70.17) v2(22.1,67.76) v2(22.07,65.81) v2(22.23,82.72) v2(22.23,80.44) v2(22.16,61.36) v2(22.24,40.52) v2(22.24,38.38) v2(22.24,35.26) v2(22.24,32.54) v2(22.27,93.16) v2(22.33,47.7) v2(22.25,30.18) v2(22.3,26.29) v2(22.35,45.9) v2(22.48,57.23) v2(22.61,73.47) v2(23.12,52.67) v2(23.13,41.4) v2(23.13,38.28) v2(23.13,35.26) v2(23.13,33.38) v2(23.11,31.22) v2(23.19,27.33) v2(23.24,12.02) v2(23.29,50.88) v2(23.34,44.02) v2(23.5,88.57) v2(23.5,81.45) v2(23.62,56.42) v2(23.91,63.7) v2(24.02,40.31) v2(24.02,38.15) v2(24.02,35.26) v2(24.02,33.56) v2(24.02,32.22) v2(24,22.68) v2(24,15.45) v2(24.13,42.4) v2(24.05,30.28) v2(24.26,19.38) v2(24.38,59.13) v2(24.38,55.83) v2(24.68,64.48) v2(24.74,23.85) v2(24.77,87.25) v2(24.77,82.72) v2(24.77,80.44) v2(24.94,41.86) v2(24.97,50.22) v2(25.02,20.14) v2(25.17,85.34) v2(25.22,54.77) v2(25.17,46) v2(25.34,39.8) v2(25.35,48.95) v2(25.35,37.8) v2(25.35,34.11) v2(25.53,81.45) v2(25.45,58.24) v2(25.48,32.06) v2(25.5,26.93) v2(25.57,93.11) v2(25.68,24.82) v2(25.91,79.81) v2(25.91,20.78) v2(26.04,91.11) v2(26.04,88.57) v2(26.01,76.26) v2(26.04,74.49) v2(26.01,53.62) v2(26.09,77.99) v2(26.09,28.25) v2(26.24,29.37) v2(26.29,60.15) v2(26.42,55.83) v2(26.42,50.37) v2(26.42,44.15) v2(26.42,41.23) v2(26.42,11.38) v2(26.72,72.74) v2(26.7,21.9) v2(27.05,58.75) v2(27.05,52.02) v2(27.05,48.21) v2(27.05,46.94) v2(27.05,37.42) v2(27.42,77.03) v2(27.38,23.14) v2(27.5,82.23) v2(27.53,78.73) v2(27.52,75.24) v2(27.66,71.77) v2(28.04,26.29) v2(27.99,18.67) v2(28.12,93.14) v2(28.14,24.29) v2(28.24,29.26) v2(28.32,15.45) v2(28.58,91.11) v2(28.58,88.57) v2(28.6,61.33) v2(28.7,72.71) v2(28.68,70.24) v2(28.83,60.15) v2(28.8,26.8) v2(28.98,82.21) v2(29.03,76.77) v2(29.08,78.78) v2(29.14,74.78) v2(29.08,30.36) v2(29.27,86.51) v2(29.49,19.1) v2(29.72,55.96) v2(29.84,58.75) v2(29.84,48.21) v2(29.84,41.35) v2(29.95,60.91) v2(29.97,52.02) v2(29.97,44.15) v2(29.97,37.42) v2(30.05,24.29) v2(30.07,20.42) v2(30.07,17.25) v2(30.4,27.1) v2(30.53,70.86) v2(30.61,82.19) v2(30.66,93.14) v2(30.73,78.76) v2(30.66,76.89) v2(30.93,72.74) v2(30.86,11.38) v2(31,59.91) v2(31.12,91.11) v2(31.12,88.57) v2(31.11,23.22) v2(31.19,21.24) v2(31.39,74.55) v2(31.37,17.26) v2(31.37,16.33) v2(31.37,15.32) v2(31.5,27.94) v2(31.62,63.71) v2(31.81,86.51) v2(31.75,66.37) v2(31.98,24.26) v2(32,18.58) v2(32.09,77.82) v2(32.18,82.29) v2(32.2,79.14) v2(32.17,76.08) v2(32.33,80.81) v2(32.54,70.3) v2(32.66,63.68) v2(32.66,58.31) v2(32.87,71.54) v2(32.97,73.03) v2(33.05,23.19) v2(33.08,75.11) v2(33.2,93.14) v2(33.15,67.26) v2(33.4,62.05) v2(33.66,91.11) v2(33.66,88.57) v2(33.79,80.34) v2(33.79,79.45) v2(33.85,77.14) v2(34.04,74.08) v2(34.29,23.24) v2(34.8,60.53) v2(34.82,26.96) v2(34.9,72.76) v2(34.95,70.33) v2(35.05,80.33) v2(35.05,79.44) v2(35.05,78.55) v2(35.53,28.48) v2(35.74,93.14) v2(35.69,59.64) v2(35.86,91.11) v2(35.94,73.98) v2(35.94,25.64) v2(35.94,24.32) v2(35.94,23) v2(35.94,21.22) v2(35.94,19.9) v2(35.94,18.58) v2(35.94,17.26) v2(35.94,16.37) v2(35.94,15.32) v2(36.07,71.54) v2(36.2,88.57) v2(36.2,86.03) v2(36.2,83.49) v2(37.16,26.96) v2(37.21,11.38) v2(37.36,72.76) v2(37.36,70.27) v2(37.59,60.56) v2(38.13,71.24) v2(38.28,73.98) v2(38.28,28.29) v2(38.53,67.23) v2(38.51,61.97) v2(38.46,35.68) v2(38.74,88.57) v2(38.99,72.08) v2(39.25,86.03) v2(39.25,83.49) v2(39.29,59.64) v2(39.56,91.11) v2(39.57,68.06) v2(39.93,93.13) v2(39.88,72.97) v2(40.08,65.68) v2(40.49,68.88) v2(40.97,66.67) v2(41.02,28.29) v2(41.02,26.96) v2(41.02,25.64) v2(41.02,24.32) v2(41.02,23) v2(41.02,21.22) v2(41.02,19.9) v2(41.02,18.58) v2(41.02,17.26) v2(41.02,16.37) v2(41.02,15.32) v2(41.28,88.57) v2(41.28,86.03) v2(41.28,83.49) v2(41.33,69.77) v2(41.38,93.13) v2(41.4,60.56) v2(41.66,64) v2(41.83,61.97) v2(41.88,67.48) v2(41.88,59.64) v2(42.29,70.55) v2(42.57,65.07) v2(42.75,68.34) v2(42.93,11.38) v2(43.28,62.48) v2(43.31,58.17) v2(43.43,65.93) v2(44.15,68.68) v2(44.27,63.44) v2(44.32,59.18) v2(45.08,67.76) v2(45.08,60.02) v2(45.19,65.91) v2(45.49,62.12) v2(45.82,57.58) v2(45.97,29.92) v2(46.1,64.64) v2(46.1,28.29) v2(46.1,26.96) v2(46.1,25.64) v2(46.1,24.32) v2(46.1,23) v2(46.1,21.22) v2(46.1,19.9) v2(46.1,18.58) v2(46.1,17.26) v2(46.1,16.37) v2(46.1,15.32) v2(46.18,67.38) v2(46.25,65.88) v2(46.43,43.92) v2(46.39,42.13) v2(47.32,63.42) v2(47.37,67.52) v2(47.42,64.64) v2(47.52,60.62) v2(47.62,29.92) v2(48.01,41.93) v2(48.01,12.02) v2(48.26,58.63) v2(48.59,43.6) v2(48.67,63.42) v2(48.69,62.04) v2(49.1,30.43) v2(49.43,45) v2(49.52,42.89) v2(49.91,51.59) v2(50.04,62.07) v2(50.09,60.62) v2(50.17,67.64) v2(50.17,57.99) v2(50.45,53.93) v2(50.47,41.75) v2(50.62,64.64) v2(50.8,63.42) v2(51.05,68.15) v2(51.18,34.57) v2(51.18,28.29) v2(51.18,26.96) v2(51.18,25.64) v2(51.18,24.32) v2(51.18,23) v2(51.18,21.22) v2(51.18,19.9) v2(51.18,18.58) v2(51.18,17.26) v2(51.18,16.37) v2(51.18,15.32) v2(51.46,60.65) v2(51.49,51.59) v2(51.82,59.26) v2(51.82,43.13) v2(51.94,65.85) v2(51.94,64.64) v2(52.17,62.04) v2(52.45,41.61) v2(52.68,63.42) v2(53.47,67.77) v2(53.47,64.64) v2(53.72,12.02) v2(53.97,44.34) v2(53.95,43.02) v2(54.2,61.94) v2(54.23,60.63) v2(54.71,48.67) v2(54.99,59.26) v2(55.4,64.64) v2(55.35,50.88) v2(56.13,63.42) v2(56.11,32.18) v2(56.26,67.52) v2(56.31,60.65) v2(56.26,28.29) v2(56.26,26.96) v2(56.26,25.64) v2(56.26,24.32) v2(56.26,23) v2(56.26,22.11) v2(56.26,21.22) v2(56.26,19.9) v2(56.26,18.58) v2(56.26,17.26) v2(56.26,16.37) v2(56.26,15.32) v2(56.72,61.94) v2(57.12,33.07) v2(57.28,59.26) v2(57.38,66.31) v2(57.53,11.38) v2(57.76,64.99) v2(58.01,32.18) v2(58.1,63.66) v2(58.47,69.19) v2(58.52,59.58) v2(58.67,62.44) v2(58.7,60.6) v2(58.83,33.07) v2(59.16,69.85) v2(59.33,68.3) v2(59.49,64.99) v2(59.63,23) v2(59.72,24.32) v2(59.66,22.11) v2(59.78,21.22) v2(59.84,16.36) v2(59.82,15.32) v2(59.87,63.66) v2(59.92,19.9) v2(59.92,18.58) v2(59.87,17.26) v2(60.05,68.99) v2(59.99,34.42) v2(60.2,67.44) v2(60.22,32.74) v2(60.19,28.29) v2(60.6,62.39) v2(60.91,68.13) v2(61.09,66.6) v2(61.15,59.42) v2(61.42,70.34) v2(61.72,34.14) v2(61.66,26.96) v2(61.77,71.62) v2(61.75,67.26) v2(61.77,63.68) v2(61.93,65.69) v2(62.04,25.64) v2(62.1,74.24) v2(62.18,62.4) v2(62.23,29.54) v2(62.26,69.14) v2(62.61,66.37) v2(63.02,24.32) v2(63.09,64.98) v2(63.25,28.4) v2(63.3,67.91) v2(63.37,75.51) v2(63.47,23) v2(63.5,22.11) v2(63.73,21.22) v2(63.79,19.9) v2(63.93,66.69) v2(63.86,31.45) v2(63.88,11.38) v2(63.98,63.66) v2(63.96,17.26) v2(64.01,16.33) v2(64.01,15.32) v2(64.14,92.66) v2(64.08,27.03) v2(64.05,18.58) v2(64.34,71.57) v2(64.26,53.03) v2(64.44,55.21) v2(64.77,76.41) v2(64.9,30.18) v2(64.87,22.58) v2(65.02,45.79) v2(65.02,43.5) v2(65.07,73.53) v2(65.18,69.13) v2(65.15,50.36) v2(65.15,48.2) v2(65.15,21.59) v2(65.25,70.38) v2(65.25,24.23) v2(65.41,83.38) v2(65.44,65.05) v2(65.41,63.66) v2(65.41,32.84) v2(65.53,80.08) v2(65.53,41.47) v2(65.48,26.42) v2(65.61,20.12) v2(65.66,67.91) v2(66.01,66.69) v2(66.04,29.03) v2(66.14,54.73) v2(66.2,91.91) v2(66.17,53.28) v2(66.19,18.8) v2(66.42,74.62) v2(66.55,31.83) v2(66.95,63.33) v2(66.95,17.63) v2(67.18,86.69) v2(67.36,16.77) v2(67.59,28.53) v2(67.67,71.57) v2(67.82,61.94) v2(67.87,30.79) v2(67.87,25.58) v2(67.98,41.46) v2(68.2,24.64) v2(68.35,76.09) v2(68.4,66.69) v2(68.45,88.59) v2(68.5,69.16) v2(68.53,64.81) v2(68.58,73.47) v2(68.55,67.91) v2(68.55,63.58) v2(68.61,53.28) v2(68.68,54.73) v2(68.71,43.12) v2(68.68,27.69) v2(68.86,23.37) v2(68.96,11.38) v2(69.34,70.35) v2(69.56,30.49) v2(69.72,16.59) v2(69.75,22.33) v2(69.88,68.85) v2(69.93,67.05) v2(69.9,65.35) v2(69.88,63.39) v2(70.13,61.92) v2(70.18,20.86) v2(70.36,86.69) v2(70.36,80.85) v2(70.47,91.93) v2(70.51,71.57) v2(70.54,28.25) v2(70.61,20.02) v2(70.69,69.77) v2(71.12,53.28) v2(71.12,43.12) v2(71.22,54.73) v2(71.25,75.25) v2(71.35,82.09) v2(71.37,65.58) v2(71.5,88.59) v2(71.53,70.66) v2(71.48,30.48) v2(71.63,28.07) v2(71.68,67.02) v2(71.78,72.92) v2(71.84,62.07) v2(72.42,25.02) v2(72.47,67.99) v2(72.47,26.98) v2(72.57,76.14) v2(72.59,73.65) v2(72.57,63.65) v2(72.8,71.9) v2(72.9,86.3) v2(72.87,80.56) v2(72.9,79.06) v2(73.03,23.7) v2(73.32,65.4) v2(73.41,68.78) v2(73.36,29.8) v2(73.53,77.41) v2(73.51,31.22) v2(73.66,82.06) v2(73.66,53.28) v2(73.84,72.99) v2(73.81,63.67) v2(73.84,61.89) v2(73.76,54.73) v2(73.79,43.12) v2(74.14,23.55) v2(74.17,84.4) v2(74.2,66.27) v2(74.3,76.12) v2(74.63,70) v2(74.7,27.28) v2(74.68,11.38) v2(74.8,86.69) v2(74.75,74.34) v2(74.85,29.39) v2(75.03,79.93) v2(75.03,76.98) v2(75.03,64.22) v2(75.03,62.4) v2(75.06,67.13) v2(75.44,75.13) v2(75.56,70.81) v2(75.56,21.16) v2(75.95,53.15) v2(76.05,54.73) v2(76.2,68.42) v2(76.33,71.95) v2(76.27,64.96) v2(76.28,62.27) v2(76.33,43.12) v2(76.4,27.08) v2(76.45,48.2) v2(76.45,45.66) v2(76.56,50.67) v2(76.68,29.26) v2(76.96,82.42) v2(76.96,26.37) v2(77.09,69.28) v2(77.34,87.07) v2(77.37,80) v2(77.39,76.17) v2(77.93,92.73) v2(77.85,12.02) v2(77.98,66.61) v2(78.28,28.96) v2(78.38,64.36) v2(78.38,62.81) v2(78.49,71.57) v2(78.61,88.84) v2(78.61,81.22) v2(78.61,69.79) v2(79.07,20.47) v2(79.27,28.68) v2(79.5,67.13) v2(79.58,63.98) v2(79.78,66.08) v2(79.88,86.94) v2(80.37,18.51) v2(80.52,76.14) v2(80.65,71.57) v2(80.65,69.66) v2(80.65,62.94) v2(80.8,67.02) v2(80.9,65.45) v2(81.15,88.84) v2(81.15,85.67) v2(81.23,22.73) v2(81.61,66.11) v2(81.81,64.53) v2(81.79,33.11) v2(81.79,31.69) v2(82.02,30.35) v2(81.99,28.92) v2(82.14,26.61) v2(82.12,20.52) v2(82.17,68.52) v2(82.27,18.51) v2(82.42,86.94) v2(82.4,60.95) v2(82.5,65.22) v2(82.45,62.1) v2(82.65,63.72) v2(82.8,71.57) v2(82.88,59.91) v2(82.93,12.02) v2(83.06,83.13) v2(83.06,80.59) v2(83.19,67.71) v2(83.29,64.41) v2(83.59,69.79) v2(83.69,88.84) v2(83.69,76.14) v2(83.82,26.61) v2(84.12,66.85) v2(84.12,62.32) v2(84.33,60.01) v2(84.63,69.26) v2(84.73,81.45) v2(84.71,26.61) v2(84.84,71.57) v2(84.89,65.91) v2(84.96,86.94) v2(84.96,19.37) v2(85.24,49.45) v2(85.32,70.5) v2(85.34,36.27) v2(85.37,63.59) v2(85.37,48.49) v2(85.47,77.92) v2(85.52,59.76) v2(85.5,57.37) v2(85.52,20.57) v2(85.6,88.84) v2(85.7,68.6) v2(85.73,55.36) v2(85.8,44.93) v2(85.78,18.46) v2(85.99,67.55) v2(86.11,40.21) v2(86.11,11.38) v2(86.23,85.67) v2(86.23,83.13) v2(86.18,41.6) v2(86.36,59.25) v2(86.52,24.84) v2(86.72,46.63) v2(86.69,22.37) v2(87.05,39.97) v2(87.12,79.7) v2(87.1,78.43) v2(87.07,77.18) v2(87.12,76.01) v2(87.1,41.67) v2(87.27,70.45) v2(87.25,69.33) v2(87.25,62.93) v2(87.43,81.12) v2(87.5,84.4) v2(87.5,60.77) v2(87.63,66.36) v2(87.6,44.94) v2(87.72,92.88) v2(87.66,27.12) v2(87.88,42.36) v2(87.88,24.88) v2(88.01,89.86) v2(88.01,39.06) v2(88.11,18.46) v2(88.27,59.5) v2(88.27,50.44) v2(88.4,80.05) v2(88.42,68.57) v2(88.43,67.55) v2(88.44,49.41) v2(88.37,48.49) v2(88.52,72.71) v2(88.77,38.91) v2(88.78,29.75) v2(88.79,28.14) v2(88.9,43.17) v2(89.03,61.92) v2(89.03,31.82) v2(89.13,24.83) v2(89.23,77.92) v2(89.15,34.11) v2(89.28,81.35) v2(89.28,19.37) v2(89.53,82.98) v2(89.53,71.06) v2(89.53,60.28) v2(89.53,22.55) v2(89.55,69.91) v2(89.63,32.8) v2(89.82,30.62) v2(89.84,28.9) v2(89.93,68.64) v2(89.89,50.34) v2(90.04,72.71) v2(90.04,66.36) v2(90.04,53.28) v2(90.04,44.94) v2(90.18,89.89) v2(90.33,85.67) v2(90.3,39.03) v2(90.35,43.17) v2(90.45,63.52) v2(90.47,18.46) v2(90.84,67.55) v2(90.83,51.43) v2(90.88,56.41) v2(91.11,38.47) v2(91.23,64.47) v2(91.31,72.97) v2(91.31,71.06) v2(91.42,70) v2(91.44,61.93) v2(91.36,46.63) v2(91.41,34.99) v2(91.54,84.5) v2(91.53,30.43) v2(91.53,27.63) v2(91.54,26.36) v2(91.63,32.8) v2(91.72,75.74) v2(91.82,19.37) v2(91.95,73.86) v2(91.97,58.23) v2(92.08,89.86) v2(92.28,50.97) v2(92.25,38.42) v2(92.45,68.57) v2(92.5,92.84) v2(92.53,43.25) v2(92.46,11.38) v2(92.71,77.54) v2(92.71,66.36) v2(92.71,65.4) v2(92.74,56.38) v2(93.01,63.49) v2(92.96,18.46) v2(93.09,71.06) v2(93.09,44.94) v2(93.2,76.13) v2(93.2,73.59) v2(93.22,53.28) v2(93.27,70) v2(93.34,38.42) v2(93.51,67.55) v2(93.5,23.44) v2(93.57,21.84) v2(93.85,79.95) v2(93.85,59.63) v2(93.85,19.38) v2(94.03,64.48) v2(94.02,48.12) v2(94.01,36.64) v2(94.08,43.22) v2(94.34,77.84) v2(94.28,57.04) v2(94.34,38.47) v2(94.49,89.73) v2(94.49,41.9) v2(94.46,40.3) v2(94.54,33.9) v2(94.54,29.1) v2(94.54,25.98) v2(94.89,65.4) v2(95.02,44.78) v2(95.07,66.39) v2(95.15,18.46) v2(95.33,47.39) v2(95.41,68.57) v2(95.54,67.55) v2(95.58,78.61) v2(95.76,84.4) v2(95.76,83.13) v2(95.76,81.22) v2(95.82,70.14) v2(95.83,20.01) v2(96.14,72.9) v2(96.19,29.96) v2(96.19,27.28) v2(96.19,25.93) v2(96.19,24.78) v2(96.27,61.54) v2(96.27,59.76) v2(96.27,38.69) v2(96.27,35.77) v2(96.44,53.26) v2(96.49,92.86) v2(96.52,71.32) v2(96.52,45.8) v2(96.77,70.05) v2(97.28,48.21) v2(97.38,63.54) v2(97.45,21.69) v2(97.54,45.41) v2(97.54,11.38) v2(97.66,86.94) v2(97.66,84.4) v2(97.66,82.49) v2(97.66,79.95) v2(97.66,61.54) v2(97.66,59.76) v2(97.79,77.28) v2(97.89,19.45) v2(97.92,18.48) v2(97.97,68.57) v2(98.09,78.64) v2(98.27,64.47) v2(98.42,40.21) v2(98.42,38.05) v2(98.42,35.64) v2(98.68,60.63) v2(98.78,31.87) v2(98.93,53.26) v2(98.88,20.8) v2(99.06,72.59) v2(99.22,78.65) v2(99.23,45.64) v2(99.23,43.32) v2(99.25,80) v2(99.48,21.69) v2(99.57,86.94) v2(99.57,84.4) v2(99.57,82.49) v2(99.57,61.54) v2(99.65,65.4) v2(99.82,71.32) v2(99.77,70.12) v2(99.82,59.43) v2(100.03,63.54) v2(100.08,92.91) v2(100.25,19.45) v2(100.3,18.51) v2(100.44,90.83) v2(100.43,30.68) v2(100.58,66.36) v2(100.66,64.51) v2(100.82,59.46) v2(100.86,72.53) v2(100.86,34) v2(100.99,74.77) v2(101.08,60.72) v2(101.16,78.53) v2(101.47,88.21) v2(101.47,41.98) v2(101.66,65.41) v2(102,77.59) v2(102.04,75.75) v2(101.98,67.51) v2(102.02,21.69) v2(102.11,81.22) v2(102.09,73.93) v2(102.11,53.28) v2(102.18,70.2) v2(102.3,46.08) v2(102.26,32.3) v2(102.34,19.45) v2(102.31,18.48) v2(102.48,59.35) v2(102.58,71.25) v2(102.74,42.61) v2(102.76,49.05) v2(102.92,78.49) v2(102.92,76.66) v2(102.94,72.87) v2(102.92,66.35) v2(103,34.1) v2(103.21,74.81) v2(103.28,63.52) v2(103.38,89.48) v2(103.38,86.94) v2(103.38,84.4) v2(103.38,82.49) v2(103.38,64.53) v2(103.55,58.66) v2(103.89,12.02) v2(103.99,70.2) v2(104.11,92.86) v2(104.07,65.4) v2(104.27,91.01) v2(104.42,67.51) v2(104.35,49.06) v2(104.56,21.69) v2(104.57,19.47) v2(104.65,53.28) v2(104.79,72.39) v2(104.78,71.32) v2(104.9,58.62) v2(104.98,18.51) v2(105.08,78.61) v2(105.13,66.36) v2(105.23,79.99) v2(105.28,88.21) v2(105.27,81.3) v2(105.36,64.53) v2(105.36,63.49) v2(105.48,60.07) v2(105.56,20.8) v2(105.92,86.94) v2(105.92,84.4) v2(105.86,70.21) v2(106.22,65.41) v2(106.18,19.74) v2(106.43,89.49) v2(106.37,72.4) v2(106.41,71.2) v2(106.64,81.28) v2(106.61,79.98) v2(106.64,78.64) v2(106.6,45.76) v2(106.64,23.16) v2(106.71,67.51) v2(106.74,60.07) v2(107.1,66.38) v2(107.17,85.78) v2(107.19,53.28) v2(107.42,64.53) v2(107.42,63.52) v2(107.51,59.43) v2(107.54,58.31) v2(107.54,57.1) v2(107.54,19.65) v2(107.7,34.23) v2(107.88,54.65) v2(108.08,78.61) v2(108.1,60.08) v2(108.11,32.6) v2(108.33,89.49) v2(108.33,37.91) v2(108.38,23.07) v2(108.37,21.75) v2(108.56,65.42) v2(108.59,51.83) v2(108.63,39.88) v2(108.7,40.9) v2(108.84,67.53) v2(108.84,35.88) v2(108.87,35.02) v2(109.09,80.59) v2(109.19,92.86) v2(109.35,77.79) v2(109.35,74.36) v2(109.37,66.46) v2(109.4,25.44) v2(109.45,30.09) v2(109.6,64.53) v2(109.58,63.49) v2(109.68,21.79) v2(109.75,71.62) v2(109.93,70.25) v2(109.91,61.62) v2(110.11,78.55) v2(110.24,53.26) v2(110.24,12.02) v2(110.26,17.59) v2(110.36,74.36) v2(110.36,73.47) v2(110.36,72.46) v2(110.36,60.9) v2(110.36,59.63) v2(110.36,50.11) v2(110.46,67.58) v2(110.49,23.95) v2(110.57,26.59) v2(110.81,85.73) v2(110.79,83.31) v2(110.82,46.65) v2(110.76,25.44) v2(110.87,91.01) v2(111,42.49) v2(111,38.68) v2(111,34.87) v2(111,31.06) v2(111.13,65.4) v2(111.25,80.59) v2(111.63,60.9) v2(111.63,59.63) v2(111.81,64.56) v2(111.81,63.52) v2(111.89,87.58) v2(111.89,70.55) v2(111.86,51.78) v2(112.01,78.55) v2(111.96,27.98) v2(112.18,76.07) v2(112.27,77.79) v2(112.29,74.06) v2(112.27,72.13) v2(112.27,48.84) v2(112.4,31.95) v2(112.37,25.77) v2(112.4,23.95) v2(112.4,19.64) v2(112.9,89.48) v2(112.9,85.67) v2(112.9,82.49) v2(112.9,60.9) v2(112.9,59.63) v2(112.9,54.55) v2(113.03,27.3) v2(113.08,70.17) v2(113.23,53.21) v2(113.16,15.57) v2(113.26,50.56) v2(113.39,29.48) v2(113.54,74.11) v2(113.49,66.46) v2(113.54,40.58) v2(113.59,75.58) v2(113.67,91.01) v2(113.67,81.35) v2(113.79,63.49) v2(113.79,35.88) v2(113.92,79.57) v2(113.87,64.56) v2(114.17,87.57) v2(114.17,84.4) v2(114.17,61.54) v2(114.17,59) v2(114.15,26.1) v2(114.35,21.66) v2(114.58,28.64) v2(114.68,77.03) v2(115.04,31.08) v2(115.06,11.13) v2(115.21,62.02) v2(115.34,75.61) v2(115.39,63.31) v2(115.57,68.65) v2(115.7,79.57) v2(115.7,59.94) v2(115.65,57.98) v2(115.65,55.14) v2(115.75,27.73) v2(115.98,51.86) v2(116.08,89.48) v2(116.08,85.67) v2(116.08,42.49) v2(116.1,30.14) v2(116.33,81.35) v2(116.46,77.03) v2(116.51,53.26) v2(116.46,32.61) v2(116.46,15.45) v2(116.61,50.46) v2(116.69,61.87) v2(116.71,59.89) v2(116.71,57.98) v2(116.71,55.11) v2(116.97,24.08) v2(117.2,75.61) v2(117.17,51.83) v2(117.22,39.24) v2(117.22,29.23) v2(117.32,49.17) v2(117.32,45.74) v2(117.32,43.58) v2(117.3,41.37) v2(117.25,37.13) v2(117.27,34.59) v2(117.38,91.19) v2(117.6,79.57) v2(117.65,66.62) v2(117.91,53.36) v2(117.91,31.95) v2(117.98,87.57) v2(117.98,82.49) v2(118.16,50.31) v2(118.34,51.83) v2(118.39,48.99) v2(118.44,34.66) v2(118.62,77.03) v2(118.62,45.66) v2(118.62,43.5) v2(118.62,41.34) v2(118.62,39.31) v2(118.62,37.15) v2(118.75,26.03) v2(118.75,16.72) v2(119,68.19) v2(119.13,73.35) v2(119.3,59.17) v2(119.41,31.23) v2(119.52,82.83) v2(119.56,87.92) v2(119.56,85.41) v2(119.63,79.57) v2(119.63,75.51) v2(119.63,45.66) v2(119.63,43.5) v2(119.63,41.34) v2(119.63,39.31) v2(119.71,37.1) v2(119.76,55.21) v2(119.79,34.59) v2(120.07,27.35) v2(120.12,21.29) v2(120.37,54.5) v2(120.53,81.58) v2(120.78,77.79) v2(121.03,86.17) v2(121.03,83.63) v2(121.38,68.37) v2(121.41,53.41) v2(121.39,26.15) v2(121.54,79.44) v2(121.51,50.21) v2(121.79,39.57) v2(121.84,33.95) v2(121.89,92.86) v2(121.89,90.32) v2(121.89,59.17) v2(121.97,41.32) v2(122.1,45.64) v2(122.1,43.43) v2(122.16,82.28) v2(122.68,21.16) v2(122.81,28.26) v2(122.86,71.78) v2(122.91,56.96) v2(122.89,51.76) v2(122.86,24.99) v2(123.03,16.01) v2(123.13,81.22) v2(123.32,77.79) v2(123.44,69.41) v2(123.78,11.91) v2(124.03,55.97) v2(124.08,79.19) v2(124.18,70.61) v2(124.43,92.86) v2(124.43,90.32) v2(124.49,75.88) v2(124.51,58.64) v2(124.62,81.19) v2(124.61,50.13) v2(124.88,15.94) v2(124.97,28.26) v2(125.15,41.14) v2(125.09,31.31) v2(125.17,46.2) v2(125.17,43.4) v2(125.17,39.29) v2(125.17,37.18) v2(125.17,34.49) v2(125.35,77.92) v2(125.6,57.63) v2(125.84,62.14) v2(125.83,60.29) v2(125.81,54.37) v2(125.88,74.47) v2(125.89,71.96) v2(125.85,68.58) v2(125.86,65.32) v2(126.07,24.62) v2(126.49,20.78) v2(126.49,11.13) v2(126.62,76.52) v2(126.97,90.3) v2(127.19,84.35) v2(127.15,81.86) v2(127.23,63.5) v2(127.23,60.96) v2(127.18,59.28) v2(127.25,73.73) v2(127.28,69.76) v2(127.28,67.2) v2(127.76,79.83) v2(128.02,19.89) v2(128.66,68.51) v2(128.66,63.43) v2(128.66,53.27) v2(128.66,48.19) v2(128.66,43.11) v2(128.66,35.49) v2(128.66,30.41) v2(128.76,92.63) v2(128.78,74.11) v2(128.81,58.6) v2(128.94,83.01) v2(128.93,78.41) v2(129.01,90.3) v2(129.01,85.38) v2(129.29,26.62) v2(129.29,23.45) v2(129.29,19.14) v2(129.29,15.59) v2(129.29,12.65) v3(67.44,51.88) v3(67.44,50.36) v3(67.44,48.84) v3(67.44,47.31) v3(67.44,45.79) v3(67.44,44.26) v3(68.96,51.88) v3(68.96,50.36) v3(68.96,48.84) v3(68.96,47.31) v3(68.96,45.79) v3(68.96,44.26) v3(70.48,51.88) v3(70.48,50.36) v3(70.48,48.84) v3(70.48,47.31) v3(70.48,45.79) v3(70.48,44.26) v3(72.01,51.88) v3(72.01,50.36) v3(72.01,48.84) v3(72.01,47.31) v3(72.01,45.79) v3(72.01,44.26) v3(73.53,51.88) v3(73.53,50.36) v3(73.53,48.84) v3(73.53,47.31) v3(73.53,45.79) v3(73.53,44.26) v3(75.06,51.88) v3(75.06,50.36) v3(75.06,48.84) v3(75.06,47.31) v3(75.06,45.79) v3(75.06,44.26)
VDD_AUDIO: length 14.2
  TOP w0.254: R66.2 99.09,70.76 106.1,70.76 106.67,70.18 R179.2 107.51,70.21 C320.1 107.55,71.47 C158.1 R48.1 107.1,73.38 106.58,73.9 U5.9
ADAC_VOUTL: length 39
  TOP w0.203: 80.04,61.79 79.82,61.58 U1.114
  TOP w0.254: C350.2 111.21,71.29 R50.1 111.24,70.33 108.96,68.06 84.5,68.06 80.04,63.6 80.04,61.79
